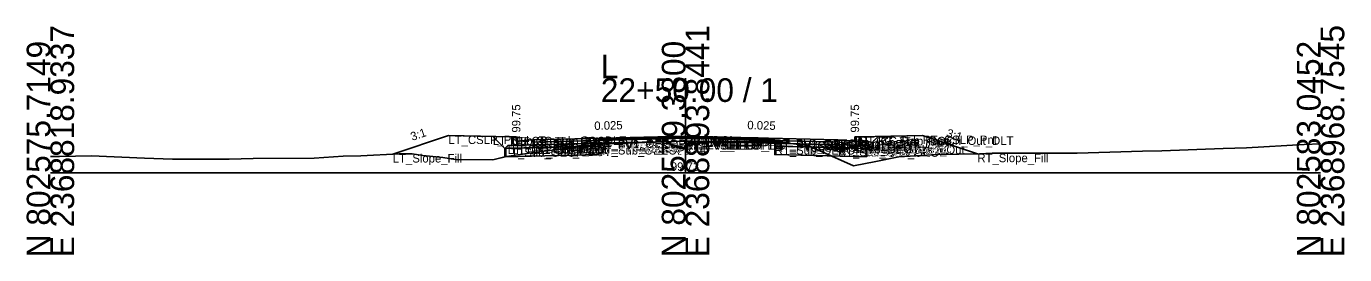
# Model space of a CAD drawing. Extents: x -26 to 8153, y -10 to 9520.
# Drawn here: x 997.2 to 1152.8, y 4490.3 to 4517.3 of the extents above; entities that cross this region are included whole.
import ezdxf

# ---------------------------------------------------------------- set-up
doc = ezdxf.new("R2010")
doc.units = 0
for name, color, linetype in [('Exist CMT Pavement', 7, 'Continuous'), ('Exist Cross Section Cell', 7, 'Continuous'), ('Exist XS Center Line Elevation Label', 7, 'Continuous'), ('Exist XS Ground Line', 7, 'Continuous'), ('Prop CMT Conc Surface', 7, 'Continuous'), ('Prop CMT Concrete Structures', 7, 'Continuous'), ('Prop CMT Pvmt Course 1', 7, 'Continuous'), ('Prop CMT Pvmt Course 1 CG', 7, 'Continuous'), ('Prop CMT Pvmt Course 1 Wedge', 7, 'Continuous'), ('Prop CMT Pvmt Course 2', 7, 'Continuous'), ('Prop CMT Pvmt Course 2 Wedge', 7, 'Continuous'), ('Prop CMT Pvmt Course 3', 7, 'Continuous'), ('Prop CMT Pvmt Course 3 Wedge', 7, 'Continuous'), ('Prop CMT Pvmt Surface', 7, 'Continuous'), ('Prop CMT Pvmt Wedge Surface 1', 7, 'Continuous'), ('Prop CMT Pvmt Wedge Surface 2', 7, 'Continuous'), ('Prop CMT Pvmt Wedge Surface 3', 7, 'Continuous'), ('Prop CMT Shallow Undercut', 7, 'Continuous'), ('Prop CMT Shallow Undercut Boundary', 7, 'Continuous'), ('Prop CMT Slope Grass', 7, 'Continuous'), ('Prop CMT Subgrade Earthwork', 7, 'Continuous'), ('Prop XS Earthwork Shape', 7, 'Continuous'), ('Prop XS Hydro Elevations', 7, 'Continuous'), ('Prop XS SE Text', 7, 'Continuous'), ('Prop XS Side Slope Text', 7, 'Continuous'), ('Prop XS Subgrade Earthwork', 7, 'Continuous'), ('Scratch_Level_2', 7, 'Continuous'), ('Scratch_Level_6', 7, 'Continuous')]:
    doc.layers.add(name, color=color, linetype=linetype)

msp = doc.modelspace()

# ---------------------------------------------------------------- linework, layer by layer
at = {"layer": 'Exist CMT Pavement'}
for p, q in [((1074.86, 4503.73), (1084.58, 4503.7)), ((1084.58, 4503.7), (1085.53, 4503.69))]:
    msp.add_line(p, q, dxfattribs=at)
msp.add_lwpolyline([(1064.72, 4503.39), (1065.61, 4503.43), (1074.86, 4503.73)], dxfattribs=at)
at = {"layer": 'Exist Cross Section Cell'}
for p, q in [((1075, 4500), (1075, 4511.18)), ((1000, 4500), (1075, 4500)), ((1075, 4500), (1150, 4500))]:
    msp.add_line(p, q, dxfattribs=at)
at = {"layer": 'Exist XS Ground Line'}
for p, q in [((1053.85, 4501.94), (1057.35, 4502.42)), ((1057.35, 4502.42), (1062.71, 4503.1)), ((1062.71, 4503.1), (1064.71, 4503.39)), ((1064.71, 4503.39), (1065.61, 4503.43)), ((1065.61, 4503.43), (1074.86, 4503.73)), ((1074.86, 4503.73), (1084.58, 4503.7)), ((1084.58, 4503.7), (1085.54, 4503.69)), ((1085.54, 4503.69), (1086.13, 4503.61)), ((1086.13, 4503.61), (1089.37, 4503.23)), ((1089.37, 4503.23), (1089.72, 4503.09)), ((1089.72, 4503.09), (1094.83, 4500.81)), ((1111.23, 4502.31), (1119.41, 4502.33)), ((1119.41, 4502.33), (1121.24, 4502.33)), ((1121.24, 4502.33), (1128.96, 4502.56)), ((1128.96, 4502.56), (1131.25, 4502.59)), ((1131.25, 4502.59), (1138.5, 4502.86)), ((1138.5, 4502.86), (1141.27, 4502.96)), ((1141.27, 4502.96), (1148.05, 4503.34)), ((1148.05, 4503.34), (1150, 4503.43)), ((1000, 4501.92), (1001.09, 4501.93)), ((1001.09, 4501.93), (1004.86, 4502.01)), ((1004.86, 4502.01), (1011.1, 4501.74)), ((1011.1, 4501.74), (1014.41, 4501.59)), ((1014.41, 4501.59), (1021.12, 4501.62)), ((1021.12, 4501.62), (1023.96, 4501.7)), ((1023.96, 4501.7), (1031.13, 4501.71)), ((1031.13, 4501.71), (1034.58, 4501.95)), ((1034.58, 4501.95), (1036.65, 4502)), ((1036.65, 4502), (1041.19, 4502.25)), ((1041.19, 4502.25), (1042.73, 4502.25)), ((1042.73, 4502.25), (1043.99, 4502.05)), ((1043.99, 4502.05), (1046.33, 4501.8)), ((1046.33, 4501.8), (1047.82, 4501.58)), ((1047.82, 4501.58), (1052.26, 4501.54)), ((1052.26, 4501.54), (1053.85, 4501.94)), ((1094.83, 4500.81), (1097.47, 4501.32)), ((1097.47, 4501.32), (1100.19, 4501.89)), ((1100.19, 4501.89), (1104.82, 4502.16)), ((1104.82, 4502.16), (1109.71, 4502.25)), ((1109.71, 4502.25), (1111.23, 4502.31))]:
    msp.add_line(p, q, dxfattribs=at)
at = {"layer": 'Prop CMT Conc Surface'}
for points in [[(1055, 4503.75), (1055, 4504.25), (1054.5, 4504.25)], [(1057, 4503.88), (1055, 4503.75)], [(1093, 4503.88), (1095, 4503.75)], [(1095, 4503.75), (1095, 4504.25), (1095.5, 4504.25)]]:
    msp.add_lwpolyline(points, dxfattribs=at)
at = {"layer": 'Prop CMT Concrete Structures'}
for points in [[(1057, 4503.88), (1055, 4503.75), (1055, 4504.25), (1054.5, 4504.25)], [(1054.5, 4504.25), (1054.5, 4503.24), (1057, 4503.3)], [(1057, 4503.3), (1057, 4503.88)], [(1093, 4503.88), (1095, 4503.75), (1095, 4504.25), (1095.5, 4504.25)], [(1095.5, 4504.25), (1095.5, 4503.24), (1093, 4503.3)], [(1093, 4503.3), (1093, 4503.88)]]:
    msp.add_lwpolyline(points, dxfattribs=at)
at = {"layer": 'Prop CMT Pvmt Course 1'}
for points in [[(1075, 4504.33), (1057, 4503.88)], [(1057, 4503.88), (1057, 4503.63)], [(1064.71, 4503.95), (1075, 4504.21)], [(1064.71, 4503.82), (1064.71, 4503.95)], [(1075, 4504.08), (1075, 4504.33)], [(1075, 4504.33), (1093, 4503.88)], [(1075, 4504.08), (1075, 4504.33)], [(1075, 4504.21), (1075, 4504.08), (1075, 4504.08)], [(1085.54, 4503.94), (1075, 4504.21)], [(1075, 4504.21), (1075, 4504.08), (1075, 4504.08)], [(1085.54, 4503.82), (1085.54, 4503.94)], [(1093, 4503.88), (1093, 4503.63)], [(1057, 4503.63), (1064.71, 4503.82)], [(1093, 4503.63), (1085.54, 4503.82)]]:
    msp.add_lwpolyline(points, dxfattribs=at)
at = {"layer": 'Prop CMT Pvmt Course 1 CG'}
for points in [[(1057, 4503.3), (1054, 4503.22), (1053.66, 4502.89)], [(1053.66, 4502.89), (1057, 4502.97)], [(1057, 4502.97), (1057, 4503.3)], [(1093, 4503.3), (1096, 4503.22), (1096.34, 4502.89)], [(1093, 4502.97), (1093, 4503.3)], [(1096.34, 4502.89), (1093, 4502.97)]]:
    msp.add_lwpolyline(points, dxfattribs=at)
at = {"layer": 'Prop CMT Pvmt Course 1 Wedge'}
for points in [[(1075, 4504.21), (1064.71, 4503.95)], [(1075, 4504.21), (1085.54, 4503.94)]]:
    msp.add_lwpolyline(points, dxfattribs=at)
at = {"layer": 'Prop CMT Pvmt Course 2'}
for points in [[(1064.71, 4503.82), (1057, 4503.63)], [(1057, 4503.63), (1057, 4503.3)], [(1057, 4503.3), (1064.71, 4503.49)], [(1064.71, 4503.49), (1064.71, 4503.82)], [(1085.54, 4503.49), (1085.54, 4503.82)], [(1085.54, 4503.82), (1093, 4503.63)], [(1093, 4503.3), (1085.54, 4503.49)], [(1093, 4503.63), (1093, 4503.3)]]:
    msp.add_lwpolyline(points, dxfattribs=at)
at = {"layer": 'Prop CMT Pvmt Course 2 Wedge'}
for points in [[(1075, 4504.08), (1064.71, 4503.82)], [(1075, 4504.08), (1085.54, 4503.82)]]:
    msp.add_lwpolyline(points, dxfattribs=at)
at = {"layer": 'Prop CMT Pvmt Course 3'}
for points in [[(1064.71, 4503.49), (1057, 4503.3)], [(1057, 4503.3), (1057, 4502.97)], [(1057, 4502.97), (1064.71, 4503.16)], [(1064.71, 4503.16), (1064.71, 4503.49)], [(1085.54, 4503.49), (1093, 4503.3)], [(1085.54, 4503.16), (1085.54, 4503.49)], [(1093, 4502.97), (1085.54, 4503.16)], [(1093, 4503.3), (1093, 4502.97)]]:
    msp.add_lwpolyline(points, dxfattribs=at)
at = {"layer": 'Prop CMT Pvmt Course 3 Wedge'}
for points in [[(1075, 4503.75), (1064.71, 4503.49)], [(1075, 4503.75), (1085.54, 4503.49)]]:
    msp.add_lwpolyline(points, dxfattribs=at)
at = {"layer": 'Prop CMT Pvmt Surface'}
for points in [[(1075, 4504.33), (1057, 4503.88)], [(1075, 4504.33), (1093, 4503.88)]]:
    msp.add_lwpolyline(points, dxfattribs=at)
at = {"layer": 'Prop CMT Pvmt Wedge Surface 1'}
for points in [[(1057, 4503.63), (1057, 4503.88)], [(1075, 4504.21), (1064.71, 4503.95)], [(1064.71, 4503.95), (1064.71, 4503.82)], [(1075, 4504.21), (1085.54, 4503.94)], [(1085.54, 4503.94), (1085.54, 4503.82)], [(1093, 4503.63), (1093, 4503.88)], [(1064.71, 4503.82), (1057, 4503.63)], [(1085.54, 4503.82), (1093, 4503.63)]]:
    msp.add_lwpolyline(points, dxfattribs=at)
at = {"layer": 'Prop CMT Pvmt Wedge Surface 2'}
for points in [[(1075, 4504.08), (1057, 4503.63)], [(1057, 4503.63), (1057, 4503.88)], [(1075, 4504.08), (1093, 4503.63)], [(1093, 4503.63), (1093, 4503.88)]]:
    msp.add_lwpolyline(points, dxfattribs=at)
at = {"layer": 'Prop CMT Pvmt Wedge Surface 3'}
for points in [[(1057, 4503.3), (1057, 4503.88)], [(1093, 4503.3), (1093, 4503.88)], [(1075, 4503.75), (1057, 4503.3)], [(1075, 4503.75), (1093, 4503.3)]]:
    msp.add_lwpolyline(points, dxfattribs=at)
at = {"layer": 'Prop CMT Shallow Undercut'}
for points in [[(1064.71, 4503.16), (1064.71, 4502.16), (1053.66, 4501.89), (1053.85, 4501.94), (1057.35, 4502.42), (1062.71, 4503.1), (1062.8, 4503.11)], [(1085.54, 4503.16), (1085.54, 4502.16), (1092.19, 4501.99), (1089.81, 4503.05)]]:
    msp.add_lwpolyline(points, close=True, dxfattribs=at)
at = {"layer": 'Prop CMT Shallow Undercut Boundary'}
for p, q in [((1053.66, 4502.89), (1064.71, 4503.16)), ((1053.66, 4502.89), (1053.66, 4501.89)), ((1064.71, 4503.16), (1064.71, 4502.16)), ((1085.54, 4503.16), (1085.54, 4502.16)), ((1085.54, 4503.16), (1096.34, 4502.89)), ((1096.34, 4502.89), (1096.34, 4501.89)), ((1053.66, 4501.89), (1064.71, 4502.16)), ((1085.54, 4502.16), (1096.34, 4501.89))]:
    msp.add_line(p, q, dxfattribs=at)
at = {"layer": 'Prop CMT Slope Grass'}
for points in [[(1054.5, 4504.25), (1047, 4504.4), (1040.43, 4502.21)], [(1095.5, 4504.25), (1103, 4504.4), (1109.47, 4502.25)]]:
    msp.add_lwpolyline(points, dxfattribs=at)
at = {"layer": 'Prop CMT Subgrade Earthwork'}
for points in [[(1057, 4502.97), (1053.66, 4502.89), (1052.25, 4504.3)], [(1093, 4502.97), (1096.34, 4502.89), (1097.75, 4504.3)], [(1064.71, 4503.16), (1057, 4502.97)], [(1064.71, 4503.16), (1064.72, 4503.39)], [(1085.54, 4503.16), (1085.53, 4503.69)], [(1085.54, 4503.16), (1093, 4502.97)]]:
    msp.add_lwpolyline(points, dxfattribs=at)
at = {"layer": 'Prop XS Earthwork Shape'}
for points in [[(1053.66, 4502.89), (1053.66, 4501.89), (1052.26, 4501.54), (1047.82, 4501.58), (1046.33, 4501.8), (1043.99, 4502.05), (1042.73, 4502.25), (1041.19, 4502.25), (1040.43, 4502.21), (1047, 4504.4), (1052.25, 4504.3)], [(1100.19, 4501.89), (1104.82, 4502.16), (1109.47, 4502.25), (1103, 4504.4), (1097.75, 4504.3), (1096.34, 4502.89), (1096.34, 4501.89), (1092.19, 4501.99), (1094.83, 4500.81), (1097.47, 4501.32)], [(1053.85, 4501.94), (1057.35, 4502.42), (1062.71, 4503.1), (1062.8, 4503.11), (1064.71, 4503.16), (1064.71, 4502.16), (1053.66, 4501.89)], [(1053.85, 4501.94), (1057.35, 4502.42), (1062.71, 4503.1), (1062.8, 4503.11), (1057, 4502.97), (1053.66, 4502.89), (1053.66, 4501.89)], [(1064.71, 4503.16), (1062.8, 4503.11), (1064.71, 4503.39), (1064.72, 4503.39)], [(1085.54, 4503.69), (1086.13, 4503.61), (1089.37, 4503.23), (1089.72, 4503.09), (1089.81, 4503.05), (1085.54, 4503.16), (1085.53, 4503.69)], [(1085.54, 4503.16), (1085.54, 4502.16), (1092.19, 4501.99), (1089.81, 4503.05)], [(1089.81, 4503.05), (1093, 4502.97), (1096.34, 4502.89), (1096.34, 4501.89), (1092.19, 4501.99)]]:
    msp.add_lwpolyline(points, close=True, dxfattribs=at)
at = {"layer": 'Prop XS Subgrade Earthwork'}
for p, q in [((1064.71, 4503.16), (1053.66, 4502.89)), ((1096.34, 4502.89), (1085.54, 4503.16))]:
    msp.add_line(p, q, dxfattribs=at)
at = {"layer": 'Scratch_Level_6'}
for points in [[(1064.71, 4503.16), (1064.71, 4502.16), (1053.66, 4501.89), (1053.85, 4501.94), (1057.35, 4502.42), (1062.71, 4503.1), (1062.8, 4503.11)], [(1085.54, 4503.16), (1085.54, 4502.16), (1092.19, 4501.99), (1089.81, 4503.05)]]:
    msp.add_lwpolyline(points, close=True, dxfattribs=at)

# ---------------------------------------------------------------- texts
at = {"layer": 'Exist Cross Section Cell'}
for s, p in [('E 2368818.9337', (1002.8, 4490)), ('E 2368893.8441', (1077.8, 4490)), ('E 2368968.7545', (1152.8, 4490)), ('N 802575.7149', (1000, 4490)), ('N 802579.3800', (1075, 4490)), ('N 802583.0452', (1150, 4490))]:
    msp.add_text(s, height=2.8, rotation=90, dxfattribs=at).set_placement(p)
for s, p in [('L', (1065, 4511.18)), ('22+50.00 / 1', (1065, 4508.38))]:
    msp.add_text(s, height=2.8, dxfattribs=at).set_placement(p)
at = {"layer": 'Exist XS Center Line Elevation Label'}
msp.add_text('99.73', height=1, dxfattribs=at).set_placement((1073.27, 4500.23))
at = {"layer": 'Prop XS Hydro Elevations'}
for p in [(1055.5, 4504.75), (1095.5, 4504.75)]:
    msp.add_text('99.75', height=1, rotation=90, dxfattribs=at).set_placement(p)
at = {"layer": 'Prop XS SE Text'}
for rotation, p in [(1.4321, (1064.24, 4505.06)), (358.5679, (1082.29, 4505.15))]:
    msp.add_text('0.025', height=1, rotation=rotation, dxfattribs=at).set_placement(p)
at = {"layer": 'Prop XS Side Slope Text'}
for rotation, p in [(18.4349, (1042.72, 4503.77)), (341.5651, (1105.72, 4504.29))]:
    msp.add_text('3:1', height=1, rotation=rotation, dxfattribs=at).set_placement(p)
at = {"layer": 'Scratch_Level_2'}
for s, p in [('LT_CSLP_Pnt', (1047, 4503.4)), ('LT_Sub_Trench_Out_DLT', (1052.25, 4503.3)), ('LT_CG_Top_BOC', (1054.5, 4503.25)), ('LT_CG_Top_Face', (1055, 4503.25)), ('LT_PV1_OEOT', (1057, 4502.88)), ('LT_PV1_OEEOP', (1064.71, 4502.95)), ('PV1_PGL', (1075, 4503.33)), ('RT_PV1_IEEOP', (1075, 4503.21)), ('LT_PV1_IEEOP', (1075, 4503.21)), ('RT_PV2_IEEOP', (1075, 4503.08)), ('LT_PV2_IEEOP', (1075, 4503.08)), ('PV2_PGL', (1075, 4503.08)), ('RT_PV1_OEEOP', (1085.54, 4502.94)), ('RT_PV1_OEOT', (1093, 4502.88)), ('RT_CG_Top_Face', (1095, 4503.25)), ('RT_CG_Top_BOC', (1095.5, 4503.25)), ('RT_Sub_Trench_Out_DLT', (1097.75, 4503.3)), ('RT_CSLP_Pnt', (1103, 4503.4)), ('LT_Sub_OEOP', (1053.66, 4501.89)), ('LT_CG1_Shelf_Out', (1054, 4502.22)), ('LT_CG_Bot_BOC', (1054.5, 4502.24)), ('LT_CG_Top_Gut', (1055, 4502.75)), ('LT_PV2_OEOT', (1057, 4502.63)), ('LT_PV3_OEOT', (1057, 4502.3)), ('LT_CG_Bot_IE', (1057, 4502.3)), ('LT_Sub_OEOT', (1057, 4501.97)), ('LT_PV2_OEEOP', (1064.71, 4502.82)), ('LT_PV3_OEEOP', (1064.71, 4502.49)), ('LT_PV_OEEOP_EG', (1064.71, 4502.39)), ('LT_Sub_OEEOP', (1064.71, 4502.16)), ('LT_PV_Sub_Tie_Out', (1064.72, 4502.39)), ('RT_PV3_IEEOP', (1075, 4502.75)), ('LT_PV3_IEEOP', (1075, 4502.75)), ('RT_PV_IEEOP_EG', (1075, 4502.73)), ('LT_PV_IEEOP_EG', (1075, 4502.73)), ('RT_PV_Sub_Tie_Out', (1085.53, 4502.69)), ('RT_PV2_OEEOP', (1085.54, 4502.82)), ('RT_PV_OEEOP_EG', (1085.54, 4502.69)), ('RT_PV3_OEEOP', (1085.54, 4502.49)), ('RT_Sub_OEEOP', (1085.54, 4502.16)), ('RT_PV2_OEOT', (1093, 4502.63)), ('RT_PV3_OEOT', (1093, 4502.3)), ('RT_CG_Bot_IE', (1093, 4502.3)), ('RT_Sub_OEOT', (1093, 4501.97)), ('RT_CG_Top_Gut', (1095, 4502.75)), ('RT_CG_Bot_BOC', (1095.5, 4502.24)), ('RT_CG1_Shelf_Out', (1096, 4502.22)), ('RT_Sub_OEOP', (1096.34, 4501.89)), ('LT_Slope_Fill', (1040.43, 4501.21)), ('RT_Slope_Fill', (1109.47, 4501.25))]:
    msp.add_text(s, height=1, dxfattribs=at).set_placement(p)

doc.saveas('drawing.dxf')
